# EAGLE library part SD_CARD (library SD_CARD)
SD Push-Push connector type B Secure Digital Memory Card kingfont Precision Industrial co., LTD. Farnell / Order Code: 4381610 http://www.farnell.com/datasheets/37839.pdf by André Mansur - Brazil - 19/11/2004 updated - 28/10/2005
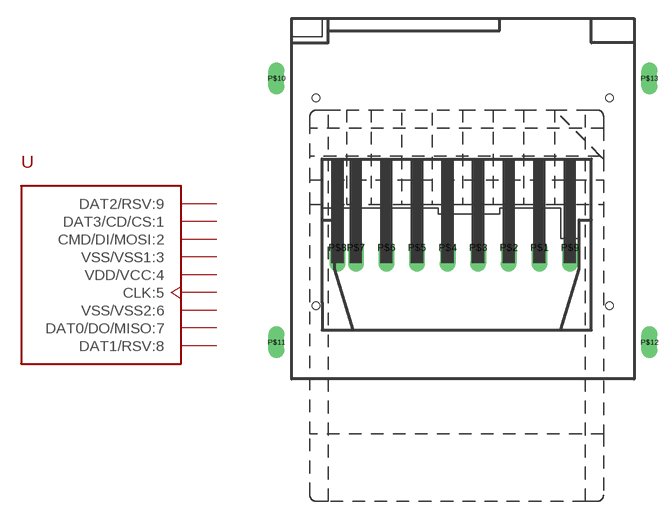
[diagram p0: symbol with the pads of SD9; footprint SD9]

Designator prefix -

## SD_CARD  [SD9]
P$1  DAT3/CD/CS:1
P$2  CMD/DI/MOSI:2
P$3  VSS/VSS1:3  pwr
P$4  VDD/VCC:4  pwr
P$5  CLK:5
P$6  VSS/VSS2:6  pwr
P$7  DAT0/DO/MISO:7
P$8  DAT1/RSV:8
P$9  DAT2/RSV:9

## Footprint SD9 (pad centres in mm)
drill 0.8 offset: P$1 6.25,-8.75; P$2 3.75,-8.75; P$3 1.25,-8.75; P$4 -1.25,-8.75; P$5 -3.75,-8.75; P$6 -6.25,-8.75; P$7 -8.75,-8.75; P$8 -10.25,-8.75; P$9 8.75,-8.75
drill 0.8 long: P$10 -15.24,5.08; P$11 -15.24,-16.51; P$12 15.24,-16.51; P$13 15.24,5.08
hole 0.6 at -12,-13.5
hole 0.6 at 12,-13.5
hole 0.6 at 12,3.5
hole 0.6 at -12,3.5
